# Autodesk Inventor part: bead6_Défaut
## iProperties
Shininess: 64.0
Length Units: 11269
Angle Units: 11279
Time Units: 11290
Mass Units: 11283
Length Display Precision: 3
Angle Display Precision: 2
Compacted: True
Part Number: bead6_Défaut
Document SubType Name: Modeling
Created: 2006-11
Material: Par défaut
Designer: profs_sti
Density: 0.0
Volumn: 0.0
Area: 0.0
PropertySet Name: Model Information
Control State: 0
Master: False
Checked Out: False
Author: profs_sti
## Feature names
1. Base1
